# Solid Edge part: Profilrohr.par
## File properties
Username: ahadarics
Dokumentum tartalom típus: 0
Author: ahadarics
Last saved by: ahadarics
Revision: 80
Sűrűség: 0,000 kg/m^3
Pontosság: 0,990
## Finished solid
Body 1: solid body, 6 faces, 6 edges, 0 vertices.
  Faces by surface: cone 2, cylinder 2, plane 2
  Edges by curve: circle 6
Bounding box of the edges (mm): 26.500 x 26.500 x 133.000, from (-13.25, -13.25, -21.5) to (13.25, 13.25, 111.5).
Cylindrical faces by radius (mm): R12.5 x1, R13.25 x1
Conical faces (half-angle, radius in mm at the cone's reference point): 15 deg R12.567 x2
Planar faces by outward normal: +z 1, -z 1
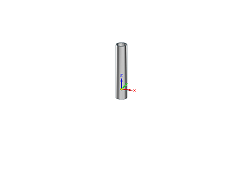
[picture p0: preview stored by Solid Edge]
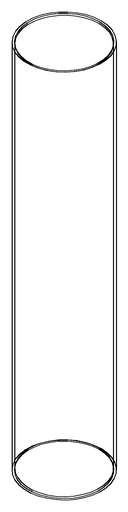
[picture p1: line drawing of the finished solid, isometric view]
